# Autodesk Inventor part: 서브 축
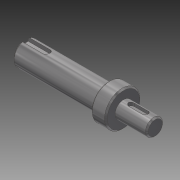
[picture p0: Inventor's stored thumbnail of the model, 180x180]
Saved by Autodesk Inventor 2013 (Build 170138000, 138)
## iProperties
Created: 2016-04
Part Number: 서브 축
Document SubType Name: Modeling
Designer: mdu
Density: 1 g/cm^3
Mass: 19.9624 g
Surface Area: 57.7178 cm^2
Volume: 19.9624 cm^3
Material: 강철, 연강
Author: mdu
Revision Number: 1
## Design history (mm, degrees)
sketch "스케치1"
  geometry: L1 (-16.331, 0)-(-108.831, 0); L2 (-16.331, 0)-(-16.331, -6); L3 (-16.331, -6)-(-38.831, -6); L4 (-38.831, -12)-(-46.5, -12); L5 (-46.5, -8.5)-(-108.831, -8.5); L6 (-108.831, -8.5)-(-108.831, 0); L7 (-46.5, -8.5)-(-46.5, -12); L8 (-38.831, -6)-(-38.831, -12); L9 (-46.5, 12.249)-(-46.5, -12.249) reference; L10 (-38.831, -17)-(-38.831, 17) reference; 2 further points
  constraints: 17 end point, 4 perpendicular, 2 collinear, 2 parallel, 1 horizontal, 1 midpoint, 1 point on line
  dimensions: "d1" = 12 diameter of L3 L1; "d2" = 24 diameter of L4 L1; "d3" = 17 diameter of L5 L1; "d18" = 22.5 distance of L2.end L3.end; "d20" = 70 distance between parallel lines of L6 L8; "d21" = 7.66872 distance of L4.start L4.end (derived)
revolve "회전1" sketch "스케치1" stored, may be unused: angle "d5" = 90 deg
feature "면 이동1"
chamfer "모따기1" distance "d6" = 0.5; stored, may be unused: second distance "d7" = 2, angle "d8" = 45 deg
node "작업 평면1"
sketch "스케치2"
  geometry: L1 (11.25, 5.5)-(11.25, -5.5) reference; L2 (-5.75, -2)-(4.25, -2); L3 (4.25, 2)-(-5.75, 2); A1 r 2 centre (4.25, 0) between (4.25, -2) and (4.25, 2); A2 r 2 centre (-5.75, 0) between (-5.75, 2) and (-5.75, -2); 2 further points
  constraints: 4 end point, 4 point on circle, 4 tangent, 2 centre point, 1 horizontal alignment, 1 midpoint, 1 parallel, 1 perpendicular
  dimensions: "d9" = 4 distance between parallel lines of L2 L3; "d10" = 14 dimension on A1 A2; "d11" = 5 distance edge to line of A1 L1
extrude "돌출1" cut sketch "스케치2" distance "d12" = 2.5; taper "d13" = 0 deg
node "작업 평면2"
sketch "스케치3"
  geometry: L1 (-31.166, -8)-(-31.166, 8) reference; L2 (-31.166, 2.5)-(-15.666, 2.5); L3 (-15.666, -2.5)-(-31.166, -2.5); A1 r 2.5 centre (-15.666, 0) between (-15.666, -2.5) and (-15.666, 2.5); 2 further points
  constraints: 4 end point, 2 perpendicular, 2 point on circle, 2 point on line, 2 tangent, 1 centre point, 1 horizontal alignment, 1 midpoint
  dimensions: "d14" = 5 distance between parallel lines of L3 L2; "d15" = 18 dimension on A1 L1
extrude "돌출2" cut sketch "스케치3" distance "d16" = 3; taper "d17" = 0 deg
node "솔리드1"
node "참조4"
node "참조5"
